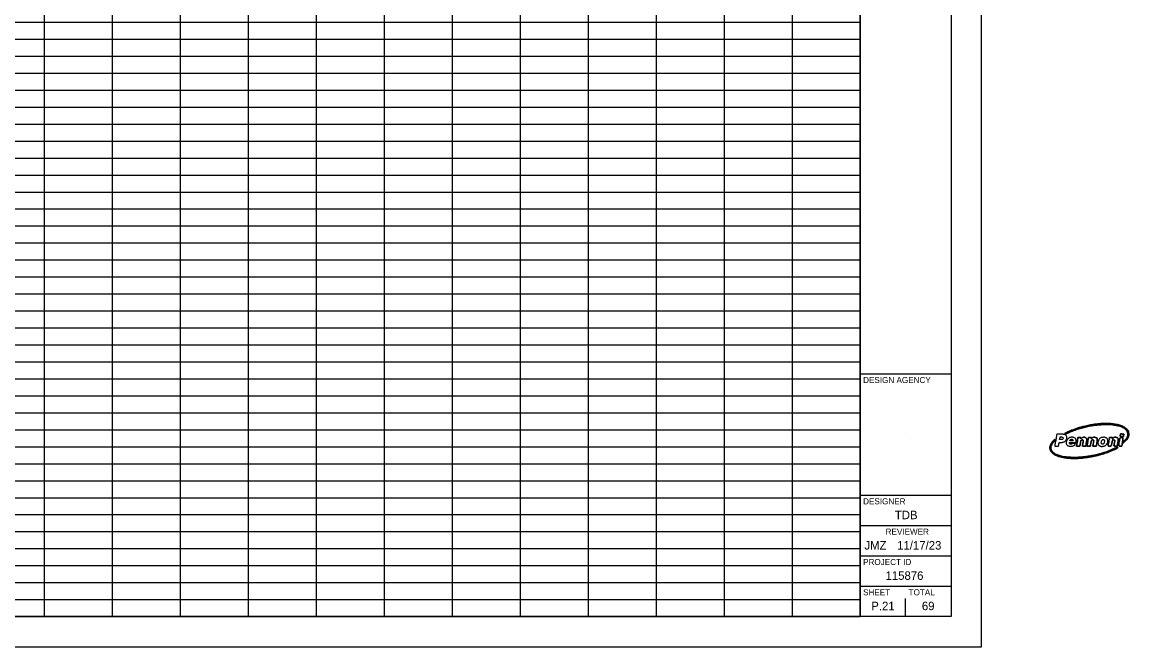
# Model space of a CAD drawing. Extents: x -0.1 to 36.3, y 0 to 22.
# Drawn here: x 18.07 to 36.31, y -0.02 to 10.28 of the extents above; entities that cross this region are included whole.
import ezdxf

# ---------------------------------------------------------------- set-up
doc = ezdxf.new("R2010")
doc.units = 0
for name, color, linetype in [('Default', 7, 'Continuous'), ('SH_Border', 7, 'Continuous'), ('SH_Cut_Line', 7, 'Continuous'), ('SH_Data', 7, 'Continuous')]:
    doc.layers.add(name, color=color, linetype=linetype)

msp = doc.modelspace()

# ---------------------------------------------------------------- linework, layer by layer
at = {"layer": 'Default'}
for p, q in [((18.43, 21.475), (18.43, 0.475)), ((19.55, 21.475), (19.55, 0.475)), ((20.671, 21.475), (20.671, 0.475)), ((21.791, 21.475), (21.791, 0.475)), ((22.912, 21.475), (22.912, 0.475)), ((24.032, 21.475), (24.032, 0.475)), ((25.153, 21.475), (25.153, 0.475)), ((26.273, 21.475), (26.273, 0.475)), ((27.394, 21.475), (27.394, 0.475)), ((28.514, 21.475), (28.514, 0.475)), ((29.635, 21.475), (29.635, 0.475)), ((30.755, 21.475), (30.755, 0.475)), ((31.876, 21.475), (31.876, 0.475)), ((1.376, 10.275), (31.876, 10.275)), ((1.376, 9.995), (31.876, 9.995)), ((1.376, 9.715), (31.876, 9.715)), ((1.376, 9.435), (31.876, 9.435)), ((1.376, 9.155), (31.876, 9.155)), ((1.376, 8.875), (31.876, 8.875)), ((1.376, 8.595), (31.876, 8.595)), ((1.376, 8.315), (31.876, 8.315)), ((1.376, 8.035), (31.876, 8.035)), ((1.376, 7.755), (31.876, 7.755)), ((1.376, 7.475), (31.876, 7.475)), ((1.376, 7.195), (31.876, 7.195)), ((1.376, 6.915), (31.876, 6.915)), ((1.376, 6.635), (31.876, 6.635)), ((1.376, 6.355), (31.876, 6.355)), ((1.376, 6.075), (31.876, 6.075)), ((1.376, 5.795), (31.876, 5.795)), ((1.376, 5.515), (31.876, 5.515)), ((1.376, 5.235), (31.876, 5.235)), ((1.376, 4.955), (31.876, 4.955)), ((1.376, 4.675), (31.876, 4.675)), ((1.376, 4.395), (31.876, 4.395)), ((1.376, 4.115), (31.876, 4.115)), ((1.376, 3.835), (31.876, 3.835)), ((1.376, 3.555), (31.876, 3.555)), ((1.376, 3.275), (31.876, 3.275)), ((1.376, 2.995), (31.876, 2.995)), ((1.376, 2.715), (31.876, 2.715)), ((1.376, 2.435), (31.876, 2.435)), ((1.376, 2.155), (31.876, 2.155)), ((1.376, 1.875), (31.876, 1.875)), ((1.376, 1.595), (31.876, 1.595)), ((1.376, 1.315), (31.876, 1.315)), ((1.376, 1.035), (31.876, 1.035)), ((1.376, 0.755), (31.876, 0.755)), ((1.376, 0.475), (31.876, 0.475))]:
    msp.add_line(p, q, dxfattribs=at)
at = {"layer": 'SH_Border'}
for p, q in [((31.876, 0.475), (31.876, 21.475)), ((31.876, 4.475), (33.376, 4.475)), ((35.385, 3.373), (35.334, 3.373)), ((31.876, 2.475), (33.376, 2.475)), ((31.876, 1.975), (33.376, 1.975)), ((31.876, 1.475), (33.376, 1.475)), ((31.876, 0.975), (33.376, 0.975))]:
    msp.add_line(p, q, dxfattribs=at)
msp.add_lwpolyline([(1.376, 21.475), (33.376, 21.475), (33.376, 0.475), (1.376, 0.475)], close=True, dxfattribs=at)
for points, degree in [([(35.244, 3.491), (35.251, 3.489), (35.257, 3.487), (35.263, 3.485), (35.265, 3.484), (35.268, 3.485), (35.27, 3.485), (35.298, 3.499), (35.327, 3.513), (35.356, 3.525), (35.397, 3.543), (35.439, 3.558), (35.482, 3.571), (35.524, 3.584), (35.567, 3.595), (35.61, 3.605), (35.649, 3.613), (35.689, 3.621), (35.73, 3.626), (35.762, 3.63), (35.794, 3.634), (35.826, 3.637), (35.851, 3.639), (35.876, 3.64), (35.902, 3.641), (35.957, 3.643), (36.012, 3.64), (36.066, 3.632), (36.096, 3.628), (36.125, 3.622), (36.154, 3.613), (36.189, 3.601), (36.223, 3.587), (36.251, 3.561), (36.266, 3.548), (36.278, 3.531), (36.283, 3.511), (36.288, 3.494), (36.289, 3.477), (36.286, 3.459), (36.283, 3.439), (36.273, 3.422), (36.26, 3.406), (36.248, 3.391), (36.234, 3.378), (36.22, 3.365), (36.218, 3.364), (36.216, 3.362), (36.216, 3.36), (36.215, 3.355), (36.214, 3.349), (36.213, 3.343), (36.212, 3.341), (36.212, 3.339), (36.212, 3.335), (36.236, 3.355), (36.258, 3.375), (36.277, 3.399), (36.286, 3.41), (36.293, 3.423), (36.299, 3.437), (36.305, 3.455), (36.306, 3.474), (36.304, 3.493), (36.3, 3.528), (36.284, 3.555), (36.258, 3.578), (36.234, 3.598), (36.206, 3.612), (36.177, 3.622), (36.14, 3.636), (36.101, 3.644), (36.062, 3.65), (36.027, 3.655), (35.992, 3.657), (35.957, 3.658), (35.901, 3.66), (35.844, 3.657), (35.788, 3.651), (35.757, 3.647), (35.726, 3.643), (35.696, 3.638), (35.65, 3.631), (35.606, 3.622), (35.561, 3.611), (35.501, 3.595), (35.441, 3.577), (35.383, 3.555), (35.342, 3.539), (35.302, 3.521), (35.263, 3.501), (35.257, 3.498), (35.251, 3.495), (35.244, 3.491)], 3), ([(35.244, 3.491), (35.251, 3.495), (35.257, 3.498), (35.263, 3.501), (35.302, 3.521), (35.342, 3.539), (35.383, 3.555), (35.441, 3.577), (35.501, 3.595), (35.561, 3.611), (35.606, 3.622), (35.65, 3.631), (35.696, 3.638), (35.726, 3.643), (35.757, 3.647), (35.788, 3.651), (35.844, 3.657), (35.901, 3.66), (35.957, 3.658), (35.992, 3.657), (36.027, 3.655), (36.062, 3.65), (36.101, 3.644), (36.14, 3.636), (36.177, 3.622), (36.206, 3.612), (36.234, 3.598), (36.258, 3.578), (36.284, 3.555), (36.3, 3.528), (36.304, 3.493), (36.306, 3.474), (36.305, 3.455), (36.299, 3.437), (36.293, 3.423), (36.286, 3.41), (36.277, 3.399), (36.258, 3.375), (36.236, 3.355), (36.212, 3.335), (36.212, 3.339), (36.212, 3.341), (36.213, 3.343), (36.214, 3.349), (36.215, 3.355), (36.216, 3.36), (36.216, 3.362), (36.218, 3.364), (36.22, 3.365), (36.234, 3.378), (36.248, 3.391), (36.26, 3.406), (36.273, 3.422), (36.283, 3.439), (36.286, 3.459), (36.289, 3.477), (36.288, 3.494), (36.283, 3.511), (36.278, 3.531), (36.266, 3.548), (36.251, 3.561), (36.223, 3.587), (36.189, 3.601), (36.154, 3.613), (36.125, 3.622), (36.096, 3.628), (36.066, 3.632), (36.012, 3.64), (35.957, 3.643), (35.902, 3.641), (35.876, 3.64), (35.851, 3.639), (35.826, 3.637), (35.794, 3.634), (35.762, 3.63), (35.73, 3.626), (35.689, 3.621), (35.649, 3.613), (35.61, 3.605), (35.567, 3.595), (35.524, 3.584), (35.482, 3.571), (35.439, 3.558), (35.397, 3.543), (35.356, 3.525), (35.327, 3.513), (35.298, 3.499), (35.27, 3.485), (35.268, 3.485), (35.265, 3.484), (35.263, 3.485), (35.257, 3.487), (35.251, 3.489), (35.244, 3.491)], 3), ([(35.255, 3.472), (35.243, 3.478), (35.229, 3.48), (35.216, 3.48), (35.184, 3.481), (35.152, 3.481), (35.12, 3.481), (35.118, 3.481), (35.117, 3.48), (35.117, 3.478), (35.113, 3.456), (35.109, 3.435), (35.106, 3.414), (35.1, 3.379), (35.093, 3.344), (35.087, 3.309), (35.086, 3.302), (35.085, 3.295), (35.084, 3.287)], 3), ([(35.157, 3.347), (35.164, 3.347), (35.171, 3.347), (35.178, 3.347), (35.191, 3.347), (35.204, 3.347), (35.217, 3.35), (35.234, 3.353), (35.249, 3.36), (35.26, 3.372), (35.275, 3.388), (35.282, 3.407), (35.282, 3.429), (35.282, 3.448), (35.273, 3.463), (35.255, 3.472)], 3), ([(36.224, 3.485), (36.221, 3.473), (36.219, 3.461), (36.217, 3.449), (36.217, 3.448), (36.215, 3.446), (36.214, 3.446), (36.197, 3.446), (36.179, 3.446), (36.161, 3.446), (36.163, 3.456), (36.165, 3.465), (36.166, 3.474), (36.167, 3.477), (36.167, 3.479), (36.168, 3.481), (36.168, 3.485), (36.169, 3.486), (36.173, 3.486), (36.188, 3.485), (36.204, 3.485), (36.219, 3.485), (36.221, 3.485), (36.222, 3.485), (36.224, 3.485)], 3), ([(36.224, 3.485), (36.222, 3.485), (36.221, 3.485), (36.219, 3.485), (36.204, 3.485), (36.188, 3.485), (36.173, 3.486), (36.169, 3.486), (36.168, 3.485), (36.168, 3.481), (36.167, 3.479), (36.167, 3.477), (36.166, 3.474), (36.165, 3.465), (36.163, 3.456), (36.161, 3.446), (36.179, 3.446), (36.197, 3.446), (36.214, 3.446), (36.215, 3.446), (36.217, 3.448), (36.217, 3.449), (36.219, 3.461), (36.221, 3.473), (36.224, 3.485)], 3), ([(36.132, 3.262), (36.132, 3.262), (36.132, 3.263), (36.132, 3.263), (36.122, 3.263), (36.112, 3.263), (36.102, 3.263), (36.099, 3.263), (36.097, 3.262), (36.094, 3.261), (36.057, 3.242), (36.019, 3.225), (35.98, 3.21), (35.922, 3.187), (35.863, 3.168), (35.803, 3.153), (35.76, 3.141), (35.716, 3.132), (35.673, 3.124), (35.648, 3.12), (35.623, 3.116), (35.598, 3.113), (35.573, 3.109), (35.547, 3.106), (35.521, 3.104), (35.497, 3.102), (35.473, 3.1), (35.449, 3.1), (35.421, 3.099), (35.392, 3.099), (35.364, 3.1), (35.333, 3.101), (35.302, 3.103), (35.271, 3.106), (35.233, 3.11), (35.196, 3.118), (35.159, 3.129), (35.128, 3.139), (35.098, 3.152), (35.071, 3.172), (35.054, 3.184), (35.04, 3.199), (35.031, 3.218), (35.019, 3.244), (35.02, 3.271), (35.031, 3.297), (35.04, 3.32), (35.054, 3.34), (35.071, 3.358), (35.076, 3.364), (35.082, 3.37), (35.082, 3.379), (35.082, 3.384), (35.084, 3.39), (35.085, 3.397), (35.083, 3.395), (35.083, 3.395), (35.082, 3.394), (35.072, 3.384), (35.063, 3.375), (35.054, 3.365), (35.034, 3.342), (35.018, 3.318), (35.01, 3.289), (35.005, 3.272), (35.004, 3.255), (35.007, 3.238), (35.012, 3.211), (35.026, 3.189), (35.046, 3.171), (35.069, 3.15), (35.095, 3.136), (35.124, 3.124), (35.171, 3.106), (35.22, 3.095), (35.27, 3.089), (35.301, 3.086), (35.332, 3.084), (35.363, 3.082), (35.406, 3.081), (35.448, 3.081), (35.49, 3.085), (35.524, 3.087), (35.559, 3.091), (35.593, 3.095), (35.623, 3.099), (35.654, 3.104), (35.685, 3.109), (35.739, 3.119), (35.793, 3.132), (35.846, 3.147), (35.891, 3.159), (35.935, 3.174), (35.979, 3.191), (36.022, 3.208), (36.064, 3.226), (36.105, 3.248), (36.114, 3.252), (36.123, 3.257), (36.132, 3.262)], 3), ([(36.132, 3.262), (36.123, 3.257), (36.114, 3.252), (36.105, 3.248), (36.064, 3.226), (36.022, 3.208), (35.979, 3.191), (35.935, 3.174), (35.891, 3.159), (35.846, 3.147), (35.793, 3.132), (35.739, 3.119), (35.685, 3.109), (35.654, 3.104), (35.623, 3.099), (35.593, 3.095), (35.559, 3.091), (35.524, 3.087), (35.49, 3.085), (35.448, 3.081), (35.406, 3.081), (35.363, 3.082), (35.332, 3.084), (35.301, 3.086), (35.27, 3.089), (35.22, 3.095), (35.171, 3.106), (35.124, 3.124), (35.095, 3.136), (35.069, 3.15), (35.046, 3.171), (35.026, 3.189), (35.012, 3.211), (35.007, 3.238), (35.004, 3.255), (35.005, 3.272), (35.01, 3.289), (35.018, 3.318), (35.034, 3.342), (35.054, 3.365), (35.063, 3.375), (35.072, 3.384), (35.082, 3.394), (35.083, 3.395), (35.083, 3.395), (35.085, 3.397), (35.084, 3.39), (35.082, 3.384), (35.082, 3.379), (35.082, 3.37), (35.076, 3.364), (35.071, 3.358), (35.054, 3.34), (35.04, 3.32), (35.031, 3.297), (35.02, 3.271), (35.019, 3.244), (35.031, 3.218), (35.04, 3.199), (35.054, 3.184), (35.071, 3.172), (35.098, 3.152), (35.128, 3.139), (35.159, 3.129), (35.196, 3.118), (35.233, 3.11), (35.271, 3.106), (35.302, 3.103), (35.333, 3.101), (35.364, 3.1), (35.392, 3.099), (35.421, 3.099), (35.449, 3.1), (35.473, 3.1), (35.497, 3.102), (35.521, 3.104), (35.547, 3.106), (35.573, 3.109), (35.598, 3.113), (35.623, 3.116), (35.648, 3.12), (35.673, 3.124), (35.716, 3.132), (35.76, 3.141), (35.803, 3.153), (35.863, 3.168), (35.922, 3.187), (35.98, 3.21), (36.019, 3.225), (36.057, 3.242), (36.094, 3.261), (36.097, 3.262), (36.099, 3.263), (36.102, 3.263), (36.112, 3.263), (36.122, 3.263), (36.132, 3.263), (36.132, 3.263), (36.132, 3.262), (36.132, 3.262)], 3), ([(35.084, 3.287), (35.085, 3.287), (35.085, 3.287), (35.086, 3.287), (35.105, 3.287), (35.124, 3.287), (35.144, 3.287), (35.146, 3.287), (35.147, 3.288), (35.147, 3.29), (35.149, 3.301), (35.151, 3.313), (35.153, 3.324), (35.154, 3.332), (35.156, 3.339), (35.157, 3.347)], 3), ([(35.165, 3.392), (35.167, 3.406), (35.17, 3.42), (35.172, 3.433), (35.172, 3.434), (35.174, 3.436), (35.174, 3.436), (35.186, 3.436), (35.197, 3.437), (35.209, 3.433), (35.219, 3.43), (35.223, 3.424), (35.221, 3.413)], 3), ([(35.221, 3.413), (35.218, 3.401), (35.209, 3.393), (35.197, 3.392), (35.186, 3.392), (35.176, 3.392), (35.165, 3.392)], 3), ([(35.437, 3.378), (35.433, 3.403), (35.42, 3.42), (35.396, 3.428), (35.383, 3.432), (35.369, 3.432), (35.356, 3.431), (35.333, 3.428), (35.314, 3.419), (35.299, 3.402), (35.285, 3.388), (35.277, 3.37), (35.275, 3.349), (35.272, 3.321), (35.284, 3.297), (35.313, 3.287), (35.329, 3.282), (35.345, 3.282), (35.362, 3.284), (35.379, 3.286), (35.396, 3.292), (35.409, 3.304), (35.417, 3.311), (35.423, 3.319), (35.428, 3.329)], 3), ([(35.428, 3.329), (35.411, 3.329), (35.394, 3.329), (35.377, 3.329), (35.376, 3.329), (35.375, 3.328), (35.374, 3.327), (35.37, 3.324), (35.366, 3.32), (35.361, 3.318), (35.345, 3.312), (35.328, 3.322), (35.329, 3.34), (35.329, 3.344), (35.33, 3.345), (35.334, 3.345), (35.366, 3.345), (35.398, 3.345), (35.43, 3.345), (35.432, 3.345), (35.434, 3.345), (35.435, 3.345)], 3), ([(35.334, 3.373), (35.336, 3.385), (35.345, 3.395), (35.358, 3.397), (35.364, 3.398), (35.369, 3.398), (35.375, 3.395), (35.382, 3.391), (35.386, 3.383), (35.385, 3.373)], 3), ([(35.435, 3.345), (35.438, 3.356), (35.438, 3.367), (35.437, 3.378)], 2), ([(35.442, 3.286), (35.443, 3.285), (35.444, 3.285), (35.444, 3.285), (35.461, 3.285), (35.478, 3.285), (35.495, 3.285), (35.498, 3.285), (35.498, 3.287), (35.498, 3.288), (35.5, 3.296), (35.501, 3.305), (35.503, 3.313), (35.506, 3.33), (35.509, 3.348), (35.512, 3.366), (35.514, 3.375), (35.519, 3.383), (35.529, 3.385), (35.542, 3.389), (35.556, 3.386), (35.553, 3.367), (35.552, 3.352), (35.549, 3.338), (35.547, 3.324), (35.544, 3.311), (35.542, 3.299), (35.54, 3.286), (35.541, 3.285), (35.541, 3.285), (35.542, 3.285), (35.559, 3.285), (35.576, 3.285), (35.593, 3.285), (35.595, 3.285), (35.596, 3.287), (35.596, 3.289), (35.6, 3.313), (35.604, 3.337), (35.608, 3.36), (35.611, 3.373), (35.613, 3.385), (35.611, 3.397), (35.609, 3.413), (35.6, 3.425), (35.584, 3.428), (35.562, 3.434), (35.542, 3.43), (35.525, 3.415), (35.522, 3.412), (35.518, 3.409), (35.514, 3.405), (35.515, 3.412), (35.516, 3.419), (35.518, 3.427), (35.501, 3.427), (35.485, 3.427), (35.469, 3.427), (35.468, 3.427), (35.467, 3.425), (35.467, 3.424), (35.466, 3.42), (35.465, 3.416), (35.464, 3.411), (35.459, 3.381), (35.454, 3.35), (35.448, 3.32), (35.446, 3.308), (35.444, 3.297), (35.442, 3.286)], 3), ([(35.442, 3.286), (35.444, 3.297), (35.446, 3.308), (35.448, 3.32), (35.454, 3.35), (35.459, 3.381), (35.464, 3.411), (35.465, 3.416), (35.466, 3.42), (35.467, 3.424), (35.467, 3.425), (35.468, 3.427), (35.469, 3.427), (35.485, 3.427), (35.501, 3.427), (35.518, 3.427), (35.516, 3.419), (35.515, 3.412), (35.514, 3.405), (35.518, 3.409), (35.522, 3.412), (35.525, 3.415), (35.542, 3.43), (35.562, 3.434), (35.584, 3.428), (35.6, 3.425), (35.609, 3.413), (35.611, 3.397), (35.613, 3.385), (35.611, 3.373), (35.608, 3.36), (35.604, 3.337), (35.6, 3.313), (35.596, 3.289), (35.596, 3.287), (35.595, 3.285), (35.593, 3.285), (35.576, 3.285), (35.559, 3.285), (35.542, 3.285), (35.541, 3.285), (35.541, 3.285), (35.54, 3.286), (35.542, 3.299), (35.544, 3.311), (35.547, 3.324), (35.549, 3.338), (35.552, 3.352), (35.553, 3.367), (35.556, 3.386), (35.542, 3.389), (35.529, 3.385), (35.519, 3.383), (35.514, 3.375), (35.512, 3.366), (35.509, 3.348), (35.506, 3.33), (35.503, 3.313), (35.501, 3.305), (35.5, 3.296), (35.498, 3.288), (35.498, 3.287), (35.498, 3.285), (35.495, 3.285), (35.478, 3.285), (35.461, 3.285), (35.444, 3.285), (35.444, 3.285), (35.443, 3.285), (35.442, 3.286)], 3), ([(35.615, 3.286), (35.616, 3.286), (35.616, 3.285), (35.616, 3.285), (35.634, 3.285), (35.651, 3.285), (35.669, 3.285), (35.67, 3.285), (35.671, 3.287), (35.671, 3.288), (35.674, 3.305), (35.677, 3.322), (35.68, 3.339), (35.682, 3.349), (35.684, 3.36), (35.687, 3.37), (35.691, 3.383), (35.703, 3.389), (35.716, 3.386), (35.722, 3.385), (35.725, 3.381), (35.726, 3.375), (35.727, 3.372), (35.727, 3.369), (35.726, 3.366), (35.725, 3.355), (35.723, 3.343), (35.721, 3.332), (35.718, 3.317), (35.716, 3.301), (35.713, 3.286), (35.713, 3.286), (35.713, 3.285), (35.713, 3.285), (35.731, 3.285), (35.749, 3.285), (35.766, 3.285), (35.767, 3.285), (35.768, 3.287), (35.769, 3.288), (35.773, 3.311), (35.777, 3.333), (35.781, 3.355), (35.782, 3.367), (35.784, 3.38), (35.784, 3.392), (35.785, 3.407), (35.779, 3.421), (35.763, 3.426), (35.742, 3.434), (35.723, 3.432), (35.704, 3.42), (35.698, 3.416), (35.693, 3.41), (35.687, 3.405), (35.688, 3.413), (35.689, 3.42), (35.691, 3.427), (35.674, 3.427), (35.658, 3.427), (35.642, 3.427), (35.64, 3.427), (35.64, 3.425), (35.639, 3.423), (35.635, 3.399), (35.631, 3.375), (35.627, 3.352), (35.623, 3.33), (35.619, 3.308), (35.615, 3.286)], 3), ([(35.615, 3.286), (35.619, 3.308), (35.623, 3.33), (35.627, 3.352), (35.631, 3.375), (35.635, 3.399), (35.639, 3.423), (35.64, 3.425), (35.64, 3.427), (35.642, 3.427), (35.658, 3.427), (35.674, 3.427), (35.691, 3.427), (35.689, 3.42), (35.688, 3.413), (35.687, 3.405), (35.693, 3.41), (35.698, 3.416), (35.704, 3.42), (35.723, 3.432), (35.742, 3.434), (35.763, 3.426), (35.779, 3.421), (35.785, 3.407), (35.784, 3.392), (35.784, 3.38), (35.782, 3.367), (35.781, 3.355), (35.777, 3.333), (35.773, 3.311), (35.769, 3.288), (35.768, 3.287), (35.767, 3.285), (35.766, 3.285), (35.749, 3.285), (35.731, 3.285), (35.713, 3.285), (35.713, 3.285), (35.713, 3.286), (35.713, 3.286), (35.716, 3.301), (35.718, 3.317), (35.721, 3.332), (35.723, 3.343), (35.725, 3.355), (35.726, 3.366), (35.727, 3.369), (35.727, 3.372), (35.726, 3.375), (35.725, 3.381), (35.722, 3.385), (35.716, 3.386), (35.703, 3.389), (35.691, 3.383), (35.687, 3.37), (35.684, 3.36), (35.682, 3.349), (35.68, 3.339), (35.677, 3.322), (35.674, 3.305), (35.671, 3.288), (35.671, 3.287), (35.67, 3.285), (35.669, 3.285), (35.651, 3.285), (35.634, 3.285), (35.616, 3.285), (35.616, 3.285), (35.616, 3.286), (35.615, 3.286)], 3), ([(35.958, 3.378), (35.957, 3.4), (35.946, 3.416), (35.926, 3.424), (35.906, 3.432), (35.886, 3.432), (35.866, 3.428), (35.842, 3.423), (35.823, 3.411), (35.81, 3.39), (35.809, 3.388), (35.808, 3.386), (35.807, 3.383), (35.805, 3.381), (35.804, 3.379), (35.803, 3.377), (35.799, 3.366), (35.796, 3.354), (35.796, 3.342), (35.796, 3.34), (35.796, 3.338), (35.796, 3.335), (35.796, 3.327), (35.798, 3.32), (35.8, 3.314), (35.801, 3.313), (35.801, 3.312), (35.802, 3.31), (35.803, 3.309), (35.803, 3.308), (35.804, 3.307), (35.806, 3.304), (35.809, 3.3), (35.812, 3.297), (35.814, 3.296), (35.816, 3.294), (35.819, 3.293), (35.819, 3.292), (35.82, 3.292), (35.82, 3.292), (35.821, 3.291), (35.823, 3.29), (35.824, 3.29), (35.826, 3.289), (35.828, 3.288), (35.83, 3.287), (35.841, 3.283), (35.852, 3.281), (35.864, 3.281)], 3), ([(35.851, 3.341), (35.852, 3.358), (35.855, 3.371), (35.864, 3.383), (35.869, 3.389), (35.875, 3.393), (35.884, 3.393), (35.892, 3.393), (35.898, 3.39), (35.901, 3.381), (35.902, 3.375), (35.903, 3.368), (35.902, 3.362)], 3), ([(35.902, 3.362), (35.902, 3.351), (35.899, 3.341), (35.893, 3.332), (35.888, 3.322), (35.878, 3.317), (35.867, 3.319), (35.861, 3.32), (35.856, 3.323), (35.854, 3.33), (35.852, 3.334), (35.852, 3.339), (35.851, 3.341)], 3), ([(35.864, 3.281), (35.871, 3.281), (35.879, 3.282), (35.886, 3.283), (35.905, 3.287), (35.922, 3.295), (35.935, 3.309), (35.952, 3.329), (35.96, 3.352), (35.958, 3.378)], 3), ([(35.986, 3.427), (35.978, 3.379), (35.97, 3.333), (35.961, 3.285), (35.98, 3.285), (35.999, 3.285), (36.017, 3.285), (36.019, 3.3), (36.022, 3.314), (36.024, 3.328), (36.027, 3.341), (36.029, 3.354), (36.032, 3.366), (36.035, 3.38), (36.045, 3.387), (36.058, 3.387), (36.067, 3.386), (36.072, 3.382), (36.073, 3.373), (36.073, 3.37), (36.073, 3.367), (36.072, 3.364), (36.069, 3.345), (36.066, 3.326), (36.063, 3.307), (36.061, 3.3), (36.06, 3.293), (36.059, 3.286), (36.078, 3.286), (36.096, 3.286), (36.114, 3.286), (36.115, 3.287), (36.115, 3.288), (36.115, 3.289), (36.119, 3.311), (36.123, 3.332), (36.126, 3.353), (36.129, 3.367), (36.132, 3.38), (36.131, 3.395), (36.129, 3.411), (36.121, 3.423), (36.105, 3.428), (36.08, 3.435), (36.058, 3.429), (36.04, 3.411), (36.038, 3.409), (36.036, 3.407), (36.034, 3.405), (36.034, 3.405), (36.033, 3.406), (36.033, 3.406), (36.034, 3.413), (36.036, 3.419), (36.037, 3.427), (36.02, 3.427), (36.003, 3.427), (35.986, 3.427)], 3), ([(35.986, 3.427), (36.003, 3.427), (36.02, 3.427), (36.037, 3.427), (36.036, 3.419), (36.034, 3.413), (36.033, 3.406), (36.033, 3.406), (36.034, 3.405), (36.034, 3.405), (36.036, 3.407), (36.038, 3.409), (36.04, 3.411), (36.058, 3.429), (36.08, 3.435), (36.105, 3.428), (36.121, 3.423), (36.129, 3.411), (36.131, 3.395), (36.132, 3.38), (36.129, 3.367), (36.126, 3.353), (36.123, 3.332), (36.119, 3.311), (36.115, 3.289), (36.115, 3.288), (36.115, 3.287), (36.114, 3.286), (36.096, 3.286), (36.078, 3.286), (36.059, 3.286), (36.06, 3.293), (36.061, 3.3), (36.063, 3.307), (36.066, 3.326), (36.069, 3.345), (36.072, 3.364), (36.073, 3.367), (36.073, 3.37), (36.073, 3.373), (36.072, 3.382), (36.067, 3.386), (36.058, 3.387), (36.045, 3.387), (36.035, 3.38), (36.032, 3.366), (36.029, 3.354), (36.027, 3.341), (36.024, 3.328), (36.022, 3.314), (36.019, 3.3), (36.017, 3.285), (35.999, 3.285), (35.98, 3.285), (35.961, 3.285), (35.97, 3.333), (35.978, 3.379), (35.986, 3.427)], 3), ([(36.189, 3.287), (36.17, 3.287), (36.152, 3.287), (36.134, 3.287), (36.142, 3.334), (36.15, 3.381), (36.158, 3.427), (36.177, 3.427), (36.195, 3.427), (36.213, 3.427), (36.205, 3.381), (36.197, 3.334), (36.189, 3.287)], 3), ([(36.189, 3.287), (36.197, 3.334), (36.205, 3.381), (36.213, 3.427), (36.195, 3.427), (36.177, 3.427), (36.158, 3.427), (36.15, 3.381), (36.142, 3.334), (36.134, 3.287), (36.152, 3.287), (36.17, 3.287), (36.189, 3.287)], 3)]:
    msp.add_open_spline(points, degree=degree, dxfattribs=at)
at = {"layer": 'SH_Cut_Line'}
msp.add_lwpolyline([(-0.124, -0.025), (33.876, -0.025), (33.876, 21.975), (-0.124, 21.975)], close=True, dxfattribs=at)
at = {"layer": 'SH_Data'}
for p, q in [((32.626, 3.475), (32.626, 3.475)), ((32.626, 0.475), (32.626, 0.775)), ((32.251, 0.65), (32.251, 0.65))]:
    msp.add_line(p, q, dxfattribs=at)

# ---------------------------------------------------------------- texts
for s, height, p in [('DESIGN AGENCY', 0.1, (31.926, 4.325)), ('DESIGNER', 0.1, (31.926, 2.325)), ('TDB', 0.14, (32.449, 2.08)), ('REVIEWER', 0.1, (32.297, 1.825)), ('JMZ', 0.14, (31.947, 1.58)), ('11/17/23', 0.14, (32.487, 1.58)), ('PROJECT ID', 0.1, (31.926, 1.325)), ('115876', 0.14, (32.295, 1.08)), ('SHEET', 0.1, (31.926, 0.825)), ('TOTAL', 0.1, (32.676, 0.825)), ('P.21', 0.14, (32.06, 0.58)), ('69', 0.14, (32.894, 0.58))]:
    msp.add_text(s, height=height, dxfattribs=at).set_placement(p)

doc.saveas('drawing.dxf')
